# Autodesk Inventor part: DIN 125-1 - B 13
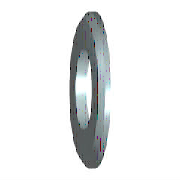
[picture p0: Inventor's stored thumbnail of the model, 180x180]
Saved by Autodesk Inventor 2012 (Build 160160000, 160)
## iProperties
Comments: To add or edit properties for Autodesk Inventor files, use iProperties.
Company: CAD-Verlag
Control State: 0
Master: False
Checked Out: False
Created: 2004-09
Part Number: DIN 125-1 - B 13
Vendor: Autodesk Inc.
Document SubType Name: Modeling
Designer: Greiling
Material: Standard
Description: Scheibe
Standard: DIN 125-1
Size Designation: B 13
Density: 1 g/cm^3
Alert: To add or edit properties for Autodesk Inventor files, use iProperties.
Shininess: 64.0
Length Units: 11269
Angle Units: 11279
Time Units: 11290
Mass Units: 11283
Length Display Precision: 3
Angle Display Precision: 2
Compacted: True
Density: 0.0
Volumn: 0.0
Area: 0.0
PropertySet Name: Model Information
Classification: un/spsc 31161807
Author: Jürgen Kronas
Revision Number: 8
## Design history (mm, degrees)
sketch "Skizze"
  geometry: C1 r 12 at (0, 0); C2 r 6.5 at (0, 0); 1 further point
  constraints: 2 centre point, 2 coincident
  dimensions: "d0" = 13 diameter of C2 (= SD1); "d1" = 24 diameter of C1 (= SD2)
extrude "Körper" new body sketch "Skizze" distance "d2" = 2.5 (= SD); taper "d3" = 0 deg
node "Volumenkörper1"
node "Volumenkörpern"
node "Oberflächenkörpern"
chamfer "Fase" distance "d4" = 0.625 (= PHH); stored, may be unused: angle "d5" = 45 deg, second distance "d8" = 0.625 (= PHH)
other parameters: "SD1" = 13 [user parameter; used in 1 equation term], "SD2" = 24 [user parameter; used in 1 equation term], "SD" = 2.5 [user parameter; used in 1 equation term], "PHH" = 0.625 [user parameter; used in 2 equation terms], "FAWI" = 45 deg [user parameter], "d6" = 0, "d7" = 0, "NND" = 12 [user parameter]
